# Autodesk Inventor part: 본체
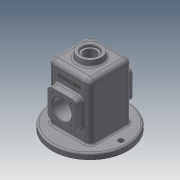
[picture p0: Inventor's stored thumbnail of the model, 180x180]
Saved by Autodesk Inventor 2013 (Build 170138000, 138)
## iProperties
Created: 2021-08
Part Number: 본체
Material: 일반
Document SubType Name: Modeling
Designer: kum
Density: 1 g/cm^3
Mass: 299.145 g
Surface Area: 947.939 cm^2
Volume: 299.145 cm^3
Author: kum
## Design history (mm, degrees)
sketch "스케치1"
  geometry: L1 (-37, 37)-(37, 37); L2 (37, 37)-(37, -37); L3 (37, -37)-(-37, -37); L4 (-37, -37)-(-37, 37); L5 (-37, 37)-(37, -37); L6 (37, 37)-(-37, -37); 1 further point
  constraints: 12 end point, 2 midpoint, 2 parallel, 1 horizontal, 1 perpendicular
  dimensions: "d0" = 74 distance of L2.end L3.end; "d1" = 74 distance of L1.end L2.end
extrude "돌출1" new body sketch "스케치1" distance "d2" = 110; taper "d3" = 0 deg
feature "쉘1" dims "d6" = 5
sketch "스케치3"
  geometry: L1 (37, 37)-(-37, 37) reference; L2 (-37, 37)-(-37, -37) reference; L3 (-37, -37)-(37, -37) reference; L4 (37, -37)-(37, 37) reference; C1 r 67 at (0, 0); 1 further point
  constraints: 1 centre point, 1 coincident
  dimensions: "d7" = 134 diameter of C1
extrude "돌출2" join sketch "스케치3" distance "d8" = 10; taper "d9" = 0 deg
sketch "스케치4"
  geometry: L1 (37, 37)-(-37, 37) reference; L2 (0, 0)-(55, 0); C1 r 67 at (0, 0) reference; C2 r 4.5 at (55, 0)
  constraints: 2 end point, 1 centre point, 1 coincident, 1 parallel
  dimensions: "d10" = 55 distance of L2.start L2.end; "d11" = 9 diameter of C2
extrude "돌출3" cut sketch "스케치4" stored distance "d12" = 10; taper "d13" = 0 deg
sketch "스케치6"
  geometry: L1 (0, -100)-(0, 0) reference; L2 (37, -110)-(37, -55); L3 (12, -30)-(62, -30); L4 (62, -30)-(62, -80); L5 (62, -80)-(12, -80); L6 (12, -80)-(12, -30); L7 (12, -30)-(62, -80); L8 (62, -30)-(12, -80)
  constraints: 14 end point, 3 parallel, 2 midpoint, 1 horizontal, 1 perpendicular
  dimensions: "d14" = 55 distance of L2.start L2.end; "d15" = 50 distance of L4.end L5.end; "d16" = 50 distance of L3.end L4.end
extrude "돌출4" join sketch "스케치6" distance "d17" = 13; taper "d18" = 0 deg
sketch "스케치8"
  geometry: L1 (20, -38)-(54, -38); L2 (54, -38)-(54, -72); L3 (20, -72)-(20, -38); L4 (20, -38)-(54, -72); L5 (54, -38)-(20, -72); L6 (104, -110)-(-30, -110) reference; L7 (37, -110)-(37, -55); L8 (5, -110)-(69, -110) reference; L9 (20, -72)-(54, -72); 6 further points
  constraints: 14 end point, 6 midpoint, 4 coincident, 2 parallel, 2 perpendicular, 1 horizontal, 1 horizontal alignment, 1 vertical alignment
  dimensions: "d23" = 34 distance of L2.end L3.start; "d24" = 34 distance of L1.end L2.end; "d64" = 55 distance of L7.start L7.end
hole "구멍1" sketch "스케치8" at (20, -38), (20, -72), (54, -72), (54, -38) diameter "d25" = 3.242; stored, may be unused: countersink angle "d29" = 90 deg, drill point angle "d31" = 118 deg; dims "d26" = 8, "d27" = 4, "d28" = 2, "d30" = 10
node "작업 평면1"
sketch "스케치10"
  geometry: C1 r 20 at (0, 0); 1 further point
  constraints: 1 centre point, 1 coincident
  dimensions: "d33" = 40 diameter of C1
extrude "돌출6" join sketch "스케치10" stored distance "d34" = 13; taper "d35" = 6 deg
sketch "스케치11"
  geometry: C1 r 20 at (0, 0) reference; 1 further point
  constraints: 1 coincident
hole "구멍2" sketch "스케치11" at (0, 0) diameter "d36" = 21; stored, may be unused: countersink angle "d40" = 90 deg, drill point angle "d42" = 118 deg; dims "d37" = 8, "d38" = 28, "d39" = 4, "d41" = 10
sketch "스케치12"
  geometry: L1 (64, 0)-(64, -105) reference; L2 (32, -55)-(32, 0); C1 r 25 at (32, -55)
  constraints: 2 end point, 1 centre point, 1 parallel
  dimensions: "d43" = 50 diameter of C1; "d60" = 55 distance of L2.end L2.start
extrude "돌출7" join sketch "스케치12" distance "d44" = 7; taper "d45" = -20 deg
sketch "스케치15"
  geometry: C1 r 22.452 at (0, 0) reference; C2 r 17 at (0, 0); 1 further point
  constraints: 1 centre point, 1 coincident
  dimensions: "d61" = 34 diameter of C2
extrude "돌출8" cut sketch "스케치15" stored distance "d62" = 7; taper "d63" = 0 deg
fillet "모깎기1" dims "d46" = 3
fillet "모깎기2" dims "d47" = 8
fillet "모깎기3" dims "d48" = 8
fillet "모깎기4" dims "d49" = 8
fillet "모깎기5" dims "d50" = 3
fillet "모깎기6" dims "d51" = 3
fillet "모깎기7" dims "d52" = 3
chamfer "모따기1" distance "d53" = 1; stored, may be unused: second distance "d54" = 2, angle "d55" = 45 deg
sketch "스케치14"
  geometry: L1 (9, 18)-(49, 18) reference; L2 (-8, 0)-(-8, -89) reference; 2 further points
  constraints: 1 other
  dimensions: "d56" = 28 distance from line of L1 point (29, -10); "d57" = 37 distance from line of L2 point (29, -10)
feature "엠보싱1" sketch "스케치14" dims "d0" = 74, "d1" = 74, "d58" = 0.5, "d59" = 0
chamfer "모따기2" distance "d65" = 1; stored, may be unused: second distance "d66" = 2, angle "d67" = 45 deg
node "솔리드1"
mirror "대칭1"
mirror "대칭2"
mirror "대칭3"
